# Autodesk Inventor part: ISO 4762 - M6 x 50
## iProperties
Comments: To add or edit properties for Autodesk Inventor files, use iProperties.
Created: 2004-08
Part Number: ISO 4762 - M6 x 50
Vendor: Autodesk Inc.
Document SubType Name: Modeling
Designer: John Blackburn
Material: Default
Description: Hexagon Socket Head Cap Screw
Standard: ISO 4762
Size Designation: M6 x 50
Alert: To add or edit properties for Autodesk Inventor files, use iProperties.
Control State: 0
Master: False
Checked Out: False
Shininess: 64.0
Length Units: 11269
Angle Units: 11279
Time Units: 11290
Mass Units: 11283
Length Display Precision: 3
Angle Display Precision: 2
Compacted: True
EGR: 1
Density: 0.0
Volumn: 0.0
Area: 0.0
PropertySet Name: Model Information
Author: John Blackburn
Revision Number: 8
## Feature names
1. Body [Revolution]
2. Slot [Extrusion]
3. Fillet1
4. Chamfer1
